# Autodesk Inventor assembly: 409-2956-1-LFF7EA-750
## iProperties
Created: 2010-06
Part Number: 409-2956-1-LFF7EA-750
Document SubType Name: Weldment
Designer: S. Boerckel
Mass: 9707.15 g
Surface Area: 4424.74 cm^2
Volume: 1235.85 cm^3
Density: 7.85466 g/cm^3
Description: RECERCULATION SPOOL
Weld Material: Welded Steel Mild
Material: WEDLMENT
Author: S. Boerckel
Revision Number: B
Subject: DEMIN WATER FORWARDING PUMP SKID-7EA
